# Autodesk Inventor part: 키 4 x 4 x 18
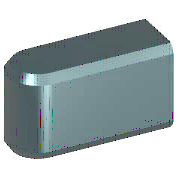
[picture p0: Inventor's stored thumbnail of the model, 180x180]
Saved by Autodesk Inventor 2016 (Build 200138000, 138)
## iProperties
IsCustomPart: 1
Created: 2012-02
Part Number: 키 4 x 4 x 18
Material: 강철, 연강
Description: 키 및 해당 키홈
Document SubType Name: Modeling
Standard: KS B 1311
Designer: mduedu
Standards Organization: KS
Language: ko-KR
Size Designation: 4 x 4 x 18
Categories: <MemberInstance><Categories><Category DisplayName="샤프트 부품" InternalName="7f7aeb1f-a693-4053-b835-cee3144e0d98" Mnemonic="SHFT"><Category DisplayName="키" Interna
Density: 1 g/cm^3
Appearance: 주황색
Author: mduedu
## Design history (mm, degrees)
sketch "스케치1"
  geometry: L1 (2, 2)-(18, 2); L2 (18, 2)-(18, -2); L3 (18, -2)-(2, -2); L4 (0, 7)-(0, -7) reference; L5 (-5, 0)-(30, 0) reference; A1 r 2 centre (2, 0) between (2, 2) and (2, -2)
  constraints: 6 end point, 3 tangent, 2 point on circle, 1 centre point, 1 horizontal, 1 parallel, 1 perpendicular, 1 point on line
  dimensions: "d0" = 2 radius of A1 (= 0.5 x PB); "d7" = 18 distance between parallel lines of L2 L4 (= NLG)
workplane "Work Plane1"
workplane "Work Plane2"
extrude "본체1" new body sketch "스케치1" taper "d3" = 0 deg; stored distance "d4" = 10
workaxis "Work Axis1"
workplane "Work Plane4"
body "Solid1"
chamfer "모따기1" distance "d8" = 0.25 (= PHH); stored, may be unused: second distance "d9" = 0.25 (= PHH), angle "d13" = 45 deg
other parameters: "d1" = -2.5 (= -PNT), "d2" = 1.5 (= PH - PNT), "NLG" = 18 [user parameter; used in 2 equation terms], "PB" = 4 [user parameter; used in 1 equation term], "PNT" = 2.5 [user parameter; used in 2 equation terms], "PH" = 4 [user parameter; used in 1 equation term], "PHH" = 0.25 [user parameter; used in 2 equation terms], "d10" = 0, "d16" = 0, "d17" = 0, "d18" = 0, "RR" = 0.08 [user parameter], "WDMAX" = 12 [user parameter], "PLB1" = 18 (= NLG) [user parameter], "PUEB" = 1.8 [user parameter]
